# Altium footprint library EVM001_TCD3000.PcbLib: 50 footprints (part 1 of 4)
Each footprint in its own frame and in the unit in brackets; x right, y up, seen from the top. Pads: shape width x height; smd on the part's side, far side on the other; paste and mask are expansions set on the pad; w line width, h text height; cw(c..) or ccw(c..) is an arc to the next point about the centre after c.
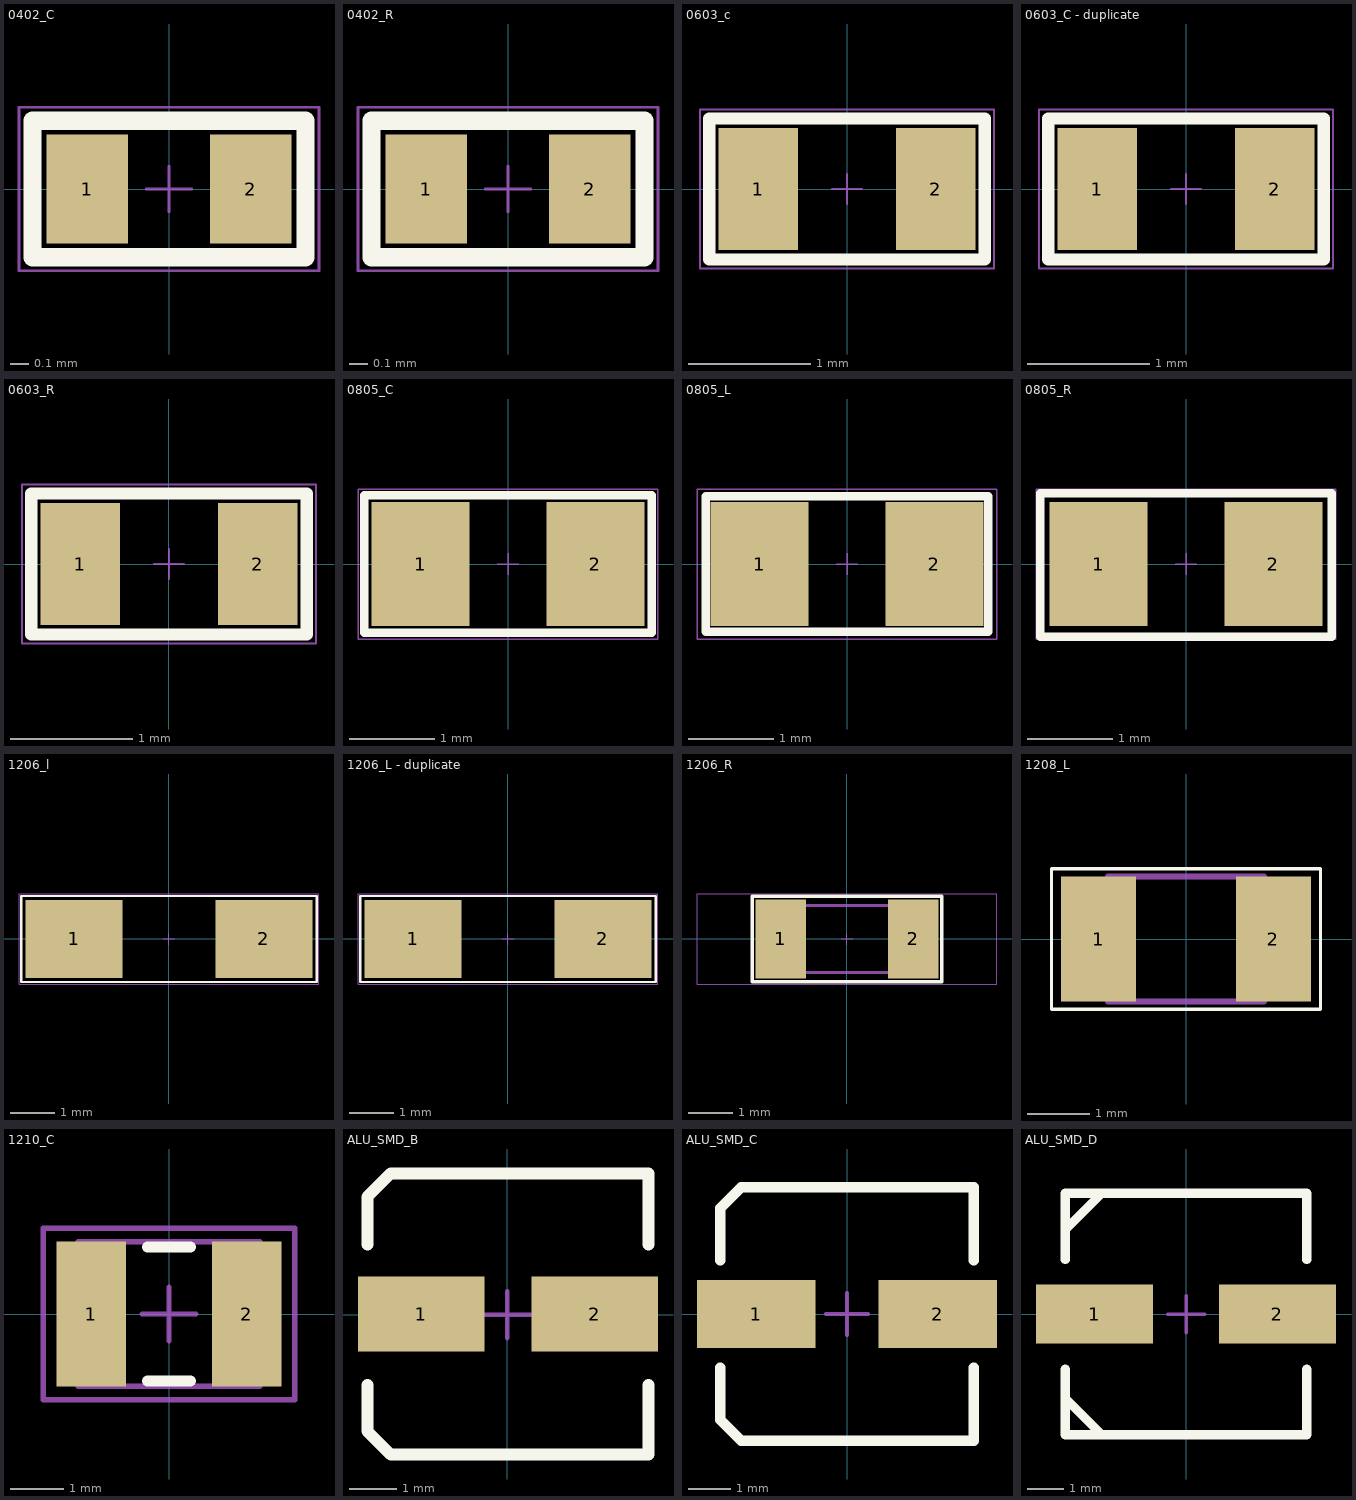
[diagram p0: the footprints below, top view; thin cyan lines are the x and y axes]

## 0402_C [mm] "Capacità SMD 0402"
height 1
pads (2):
  rect 0.45x0.6 smd: 1(-0.45,0) 2(0.45,0)
Top Overlay:
  lines w0.1: -0.75,-0.375 0.75,-0.375 0.75,0.375 -0.75,0.375 -0.75,-0.375
Mechanical 15:
  lines w0.015: -0.125,0 0.125,0 ; 0,-0.125 0,0.125 ; -0.825,-0.45 0.825,-0.45 0.825,0.45 -0.825,0.45 -0.825,-0.45
3D body: height 0.5, standoff 0, extent -0.5,-0.25 0.5,0.25

## 0402_R [mm] "Resistenza SMD 0402"
height 1
pads (2):
  rect 0.45x0.6 smd: 1(-0.45,0) 2(0.45,0)
Top Overlay:
  lines w0.1: -0.75,-0.375 0.75,-0.375 0.75,0.375 -0.75,0.375 -0.75,-0.375
Mechanical 15:
  lines w0.015: -0.125,0 0.125,0 ; 0,-0.125 0,0.125 ; -0.825,-0.45 -0.825,0.45 0.825,0.45 0.825,-0.45 -0.825,-0.45
3D body: height 0.3, standoff 0, extent -0.5,-0.25 0.5,0.25

## 0603_c [mm] "Capacità SMD 0603"
height 1
pads (2):
  rect 0.65x1 smd: 1(-0.725,0) 2(0.725,0)
Top Overlay:
  lines w0.1: -1.125,-0.575 1.125,-0.575 1.125,0.575 -1.125,0.575 -1.125,-0.575
Mechanical 15:
  lines w0.015: -0.125,0 0.125,0 ; 0,-0.125 0,0.125 ; -1.2,-0.65 -1.2,0.65 1.2,0.65 1.2,-0.65 -1.2,-0.65
3D body: height 0.8, standoff 0, extent -0.8,-0.475 0.8,0.475

## 0603_C - duplicate [mm]
pads (2):
  rect 0.65x1 smd: 1(-0.725,0) 2(0.725,0)
Top Overlay:
  lines w0.1: -1.125,-0.575 -1.125,0.575 1.125,0.575 1.125,-0.575 -1.125,-0.575
Mechanical 15:
  lines w0.015: -0.125,0 0.125,0 ; 0,-0.125 0,0.125 ; -1.2,-0.65 1.2,-0.65 1.2,0.65 -1.2,0.65 -1.2,-0.65
3D body: height 0.8, standoff 0, extent -0.8,-0.475 0.8,0.475

## 0603_R [mm] "Resistenza SMD 0603"
height 1
pads (2):
  rect 0.65x1 smd: 1(-0.725,0) 2(0.725,0)
Top Overlay:
  lines w0.1: -1.125,-0.575 1.125,-0.575 1.125,0.575 -1.125,0.575 -1.125,-0.575
Mechanical 15:
  lines w0.015: -0.125,0 0.125,0 ; 0,-0.125 0,0.125 ; -1.2,-0.65 -1.2,0.65 1.2,0.65 1.2,-0.65 -1.2,-0.65
3D body: height 0.4, standoff 0, extent -0.79,-0.4 0.81,0.4

## 0805_C [mm] "Capacità SMD 0805"
height 1
pads (2):
  rect 1.14x1.45 smd: 1(-1.02,0) 2(1.02,0)
Top Overlay:
  lines w0.1: -1.675,-0.8 1.675,-0.8 1.675,0.8 -1.675,0.8 -1.675,-0.8
Mechanical 15:
  lines w0.015: -0.125,0 0.125,0 ; 0,-0.125 0,0.125 ; -1.75,-0.875 -1.75,0.875 1.75,0.875 1.75,-0.875 -1.75,-0.875
3D body: height 0.78, standoff 0, extent -1,-0.63 1,0.62

## 0805_L [mm] "Ferrite SMD 0805"
height 1
pads (2):
  rect 1.14x1.45 smd: 1(-1.02,0) 2(1.02,0)
Top Overlay:
  lines w0.1: -1.65,-0.79 1.65,-0.79 1.65,0.79 -1.65,0.79 -1.65,-0.79
Mechanical 15:
  lines w0.015: -0.125,0 0.125,0 ; 0,-0.125 0,0.125 ; -1.75,-0.875 -1.75,0.875 1.75,0.875 1.75,-0.875 -1.75,-0.875
3D body: height 0.79, standoff 0.01, extent -1,-0.625 1,0.625

## 0805_R [mm] "Resistenza SMD 0805"
height 1
pads (2):
  rect 1.14x1.45 smd: 1(-1.02,0) 2(1.02,0)
Top Overlay:
  lines w0.1: -1.7,-0.85 1.7,-0.85 1.7,0.825 -1.7,0.825 -1.7,-0.85
Mechanical 15:
  lines w0.015: -0.125,0 0.125,0 ; 0,-0.125 0,0.125 ; -1.75,-0.875 -1.75,0.875 1.75,0.875 1.75,-0.875 -1.75,-0.875
3D body: height 0.48, standoff 0.01, extent -1,-0.626 1,0.626

## 1206_l [mm]
pads (2):
  rect 2.2x1.778 smd: 1(-2.15,0) 2(2.15,0)
Top Overlay:
  lines w0.05: -3.35,-0.975 -3.35,0.975 3.35,0.975 3.35,-0.975 -3.35,-0.975
Mechanical 15:
  lines w0.015: -0.125,0 0.125,0 ; 0,-0.125 0,0.125 ; -3.4,-1.025 3.4,-1.025 3.4,1.025 -3.4,1.025 -3.4,-1.025

## 1206_L - duplicate [mm]
pads (2):
  rect 2.2x1.778 smd: 1(-2.15,0) 2(2.15,0)
Top Overlay:
  lines w0.05: -3.35,-0.975 -3.35,0.975 3.35,0.975 3.35,-0.975 -3.35,-0.975
Mechanical 15:
  lines w0.015: -0.125,0 0.125,0 ; 0,-0.125 0,0.125 ; -3.4,-1.025 3.4,-1.025 3.4,1.025 -3.4,1.025 -3.4,-1.025

## 1206_R [mm] "Chip Resistor 120x60mils"
pads (2):
  rect 1.15x1.8 smd: 1(-1.5,0) 2(1.5,0)
Top Overlay:
  lines w0.076: -2.15,-0.97 -2.15,0.97 2.15,0.97 2.15,-0.97 -2.15,-0.97
Mechanical 13:
  lines w0.076: -1.7,-0.76 -1.7,0.76 1.7,0.76 1.7,-0.76 -1.7,-0.76
Mechanical 15:
  lines w0.015: -0.125,0 0.125,0 ; 0,-0.125 0,0.125 ; -3.4,-1.025 3.4,-1.025 3.4,1.025 -3.4,1.025 -3.4,-1.025
3D body: height 0.55, standoff 0, extent -1.6,-0.8 1.6,0.8

## 1208_L [mm]
pads (2):
  rect 1.2x2 smd: 1(-1.4,0) 2(1.4,0)
Top Overlay:
  lines w0.05: -2.15,-1.125 -2.15,1.125 2.15,1.125 2.15,-1.125 -2.15,-1.125
Mechanical 10:
  lines w0.1: -1.25,-1 -1.25,1 1.25,1 1.25,-1 -1.25,-1
3D body: height 0.9, standoff 0, extent -1.25,-1 1.25,1

## 1210_C [mm] "Chip Capacitor, Body 3.2x2.5mm, IPC Medium Density"
height 1.35
pads (2):
  rect 1.3x2.7 smd: 1(-1.45,0) 2(1.45,0)
Top Overlay:
  lines w0.2: -0.4,-1.25 0.4,-1.25 ; -0.4,1.25 0.4,1.25
Mechanical 13:
  lines w0.1: -1.7,-1.35 1.7,-1.35 1.7,1.35 -1.7,1.35 -1.7,-1.35
Mechanical 15:
  lines w0.1: -0.5,0 0.5,0 ; 0,-0.5 0,0.5 ; -2.35,-1.6 2.35,-1.6 2.35,1.6 -2.35,1.6 -2.35,-1.6
3D body: height 2.5, standoff 0, extent -1.6,-1.25 1.6,1.25

## ALU_SMD_B [mm]
pads (2):
  rect 2.7x1.6 smd: 1(-1.834,0.013) 2(1.866,0.013)
Top Overlay:
  lines w0.254: -2.984,-1.5 -2.984,-2.487 -2.484,-2.987 3.016,-2.987 3.016,-1.5 ; -2.984,1.5 -2.984,2.513 -2.484,3.013 0.016,3.013 3.016,3.013 3.016,1.5
Mechanical 15:
  lines w0.1: -0.5,0 0.5,0 ; 0,-0.5 0,0.5
3D body: height 5.4, standoff 0, extent -2.3,-2.15 2.3,2.15

## ALU_SMD_C [mm]
pads (2):
  rect 2.8x1.6 smd: 1(-2.15,0) 2(2.15,0)
Top Overlay:
  lines w0.254: -3,-1.27 -3,-2.5 -2.5,-3 3,-3 3,-1.27 ; -3,1.27 -3,2.5 -2.5,3 0,3 3,3 3,1.27
Mechanical 15:
  lines w0.1: -0.5,0 0.5,0 ; 0,-0.5 0,0.5
3D body: height 5.41, standoff 0, extent -2.95,-2.65 2.95,2.65

## ALU_SMD_D [mm]
pads (2):
  rect 3.2x1.6 smd: 1(-2.504,0.008) 2(2.496,0.008)
Top Overlay:
  lines w0.254: -3.304,-2.292 -2.304,-3.292 ; -3.304,-1.5 -3.304,-3.292 3.296,-3.292 3.296,-1.5 ; -3.304,1.5 -3.304,3.308 3.296,3.308 3.296,1.5 ; -3.304,2.308 -2.304,3.308
Mechanical 15:
  lines w0.1: -0.5,0 0.5,0 ; 0,-0.5 0,0.5
3D body: height 5.4, standoff 0, extent -3.5,-3.3 3.5,3.3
